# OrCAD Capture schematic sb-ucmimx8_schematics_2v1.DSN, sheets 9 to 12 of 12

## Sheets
9 08. PCIe: size A3; title: SB-UCM-iMX8M    08. PCIe; note: 8000103001
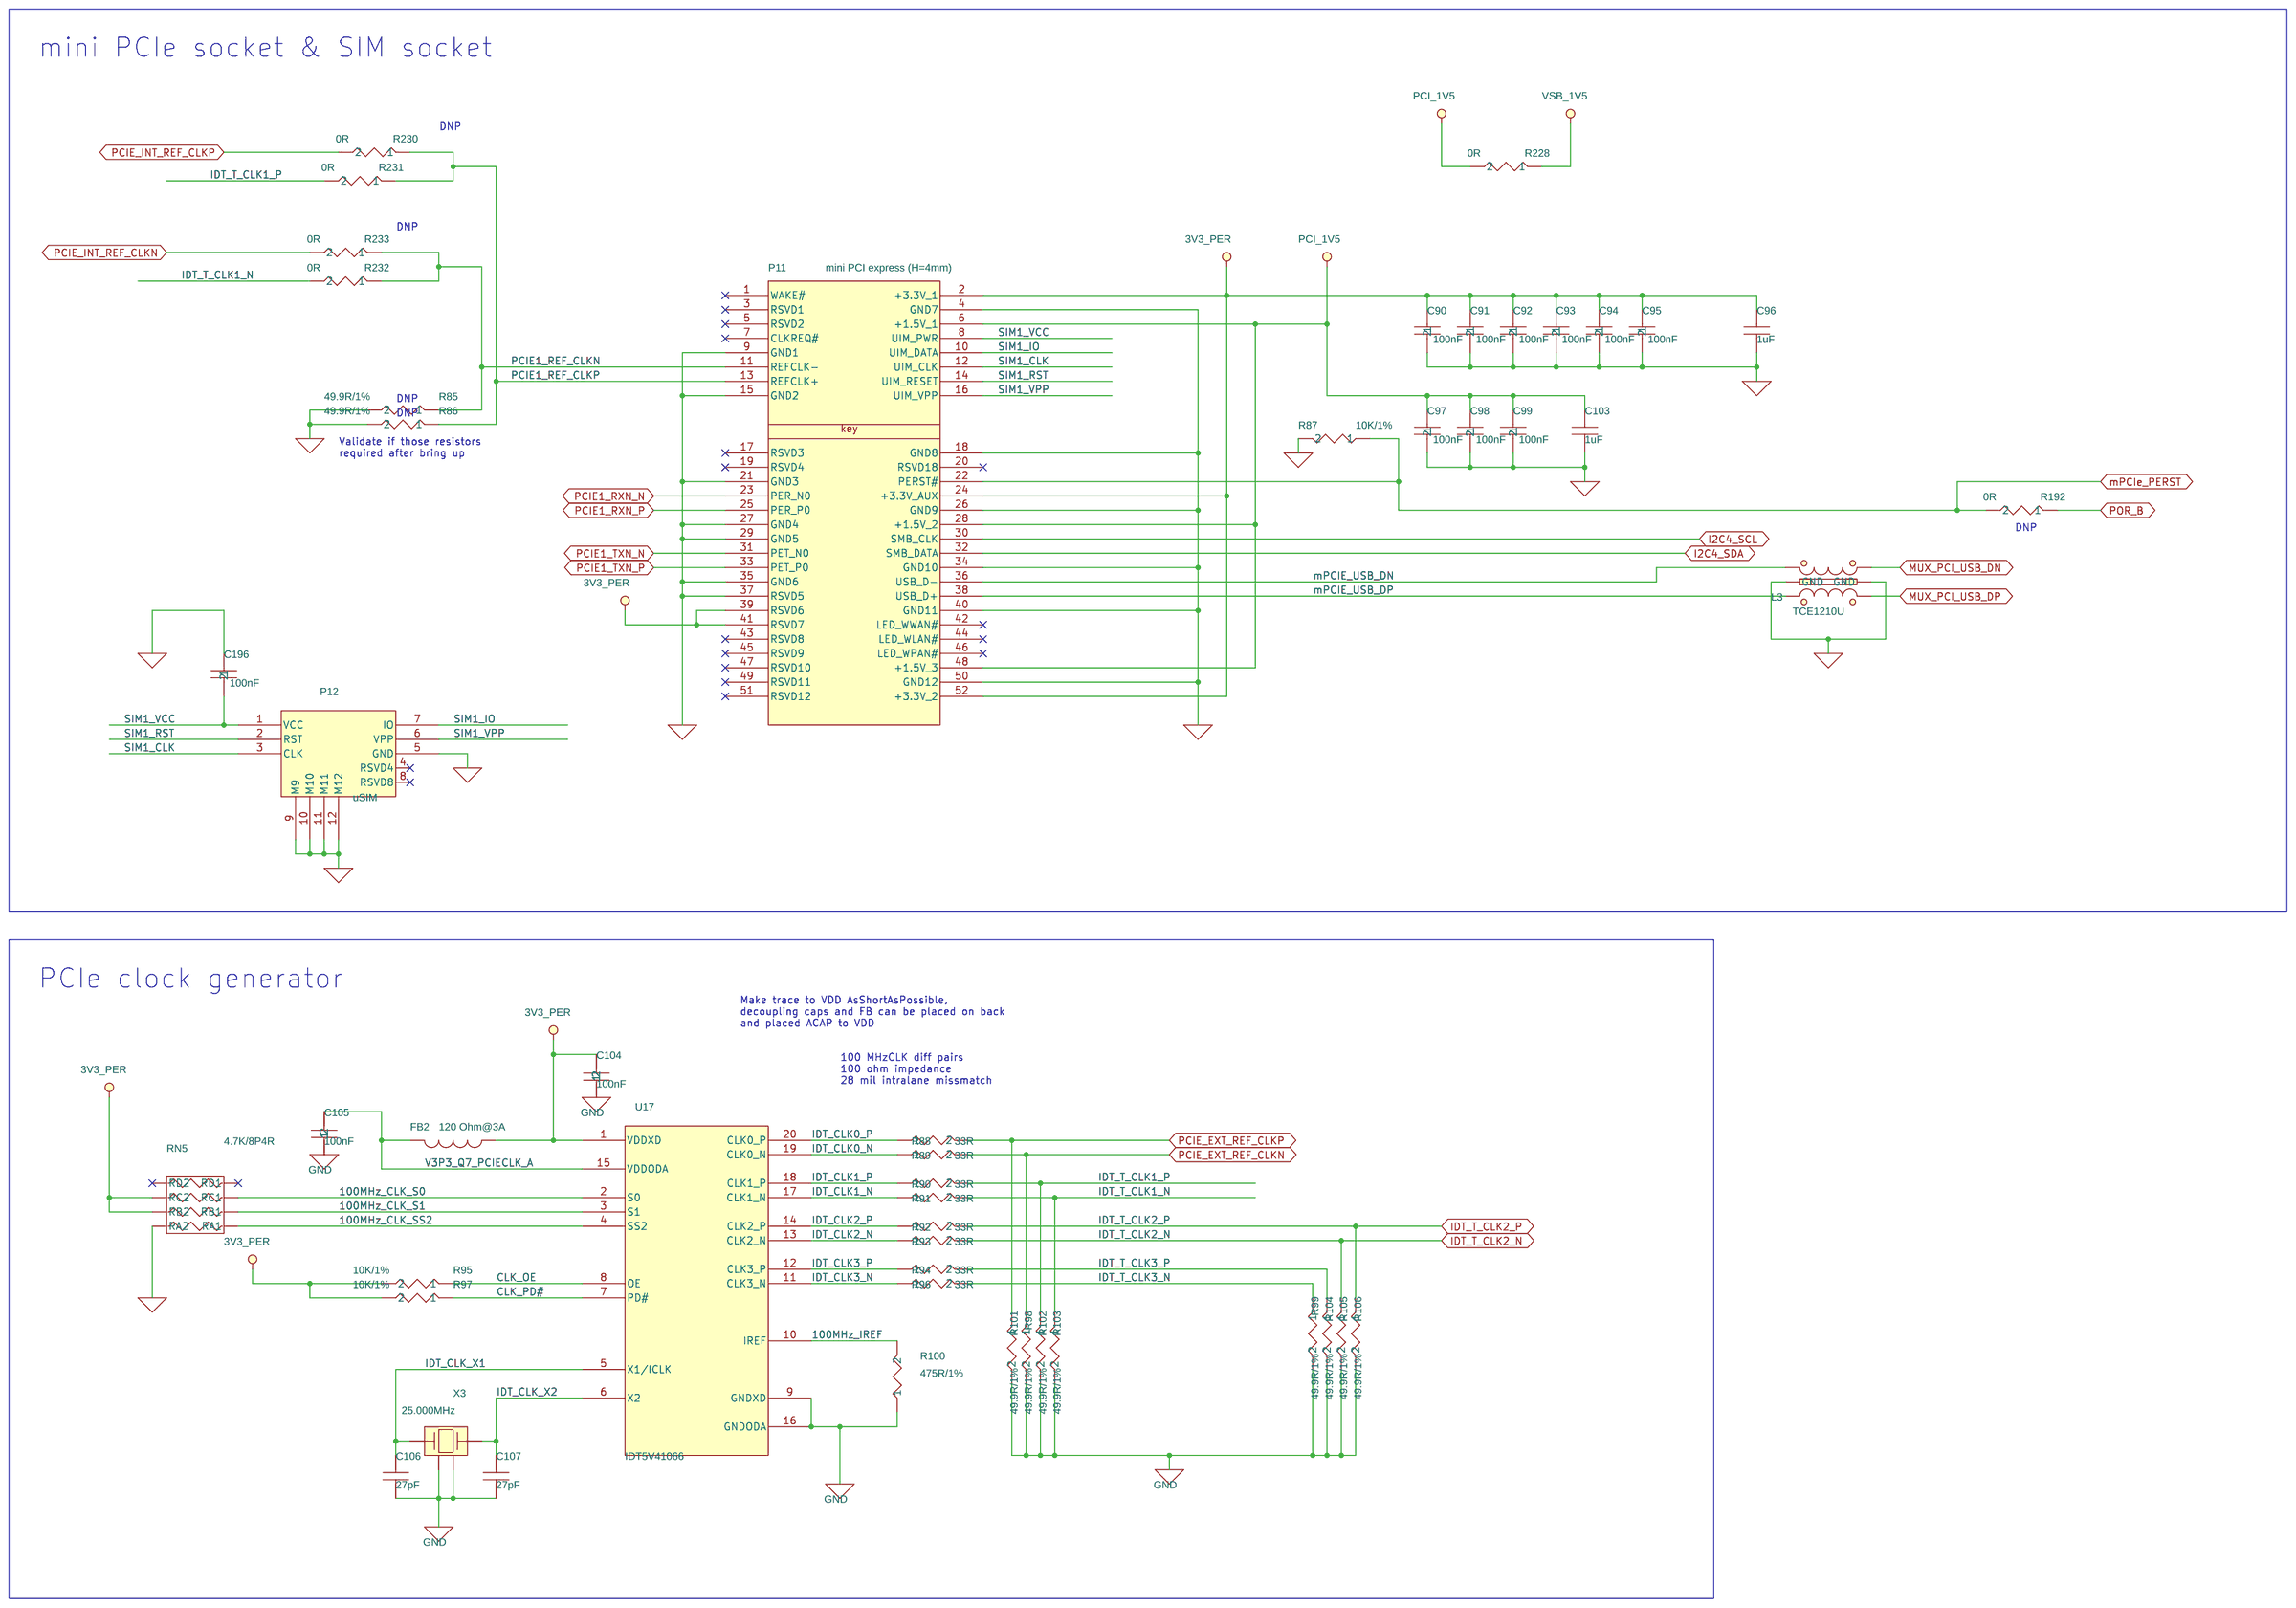
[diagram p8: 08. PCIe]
10 09. Power: size C; title: SB-UCM-iMX8M    09. POWER; note: 8000103001
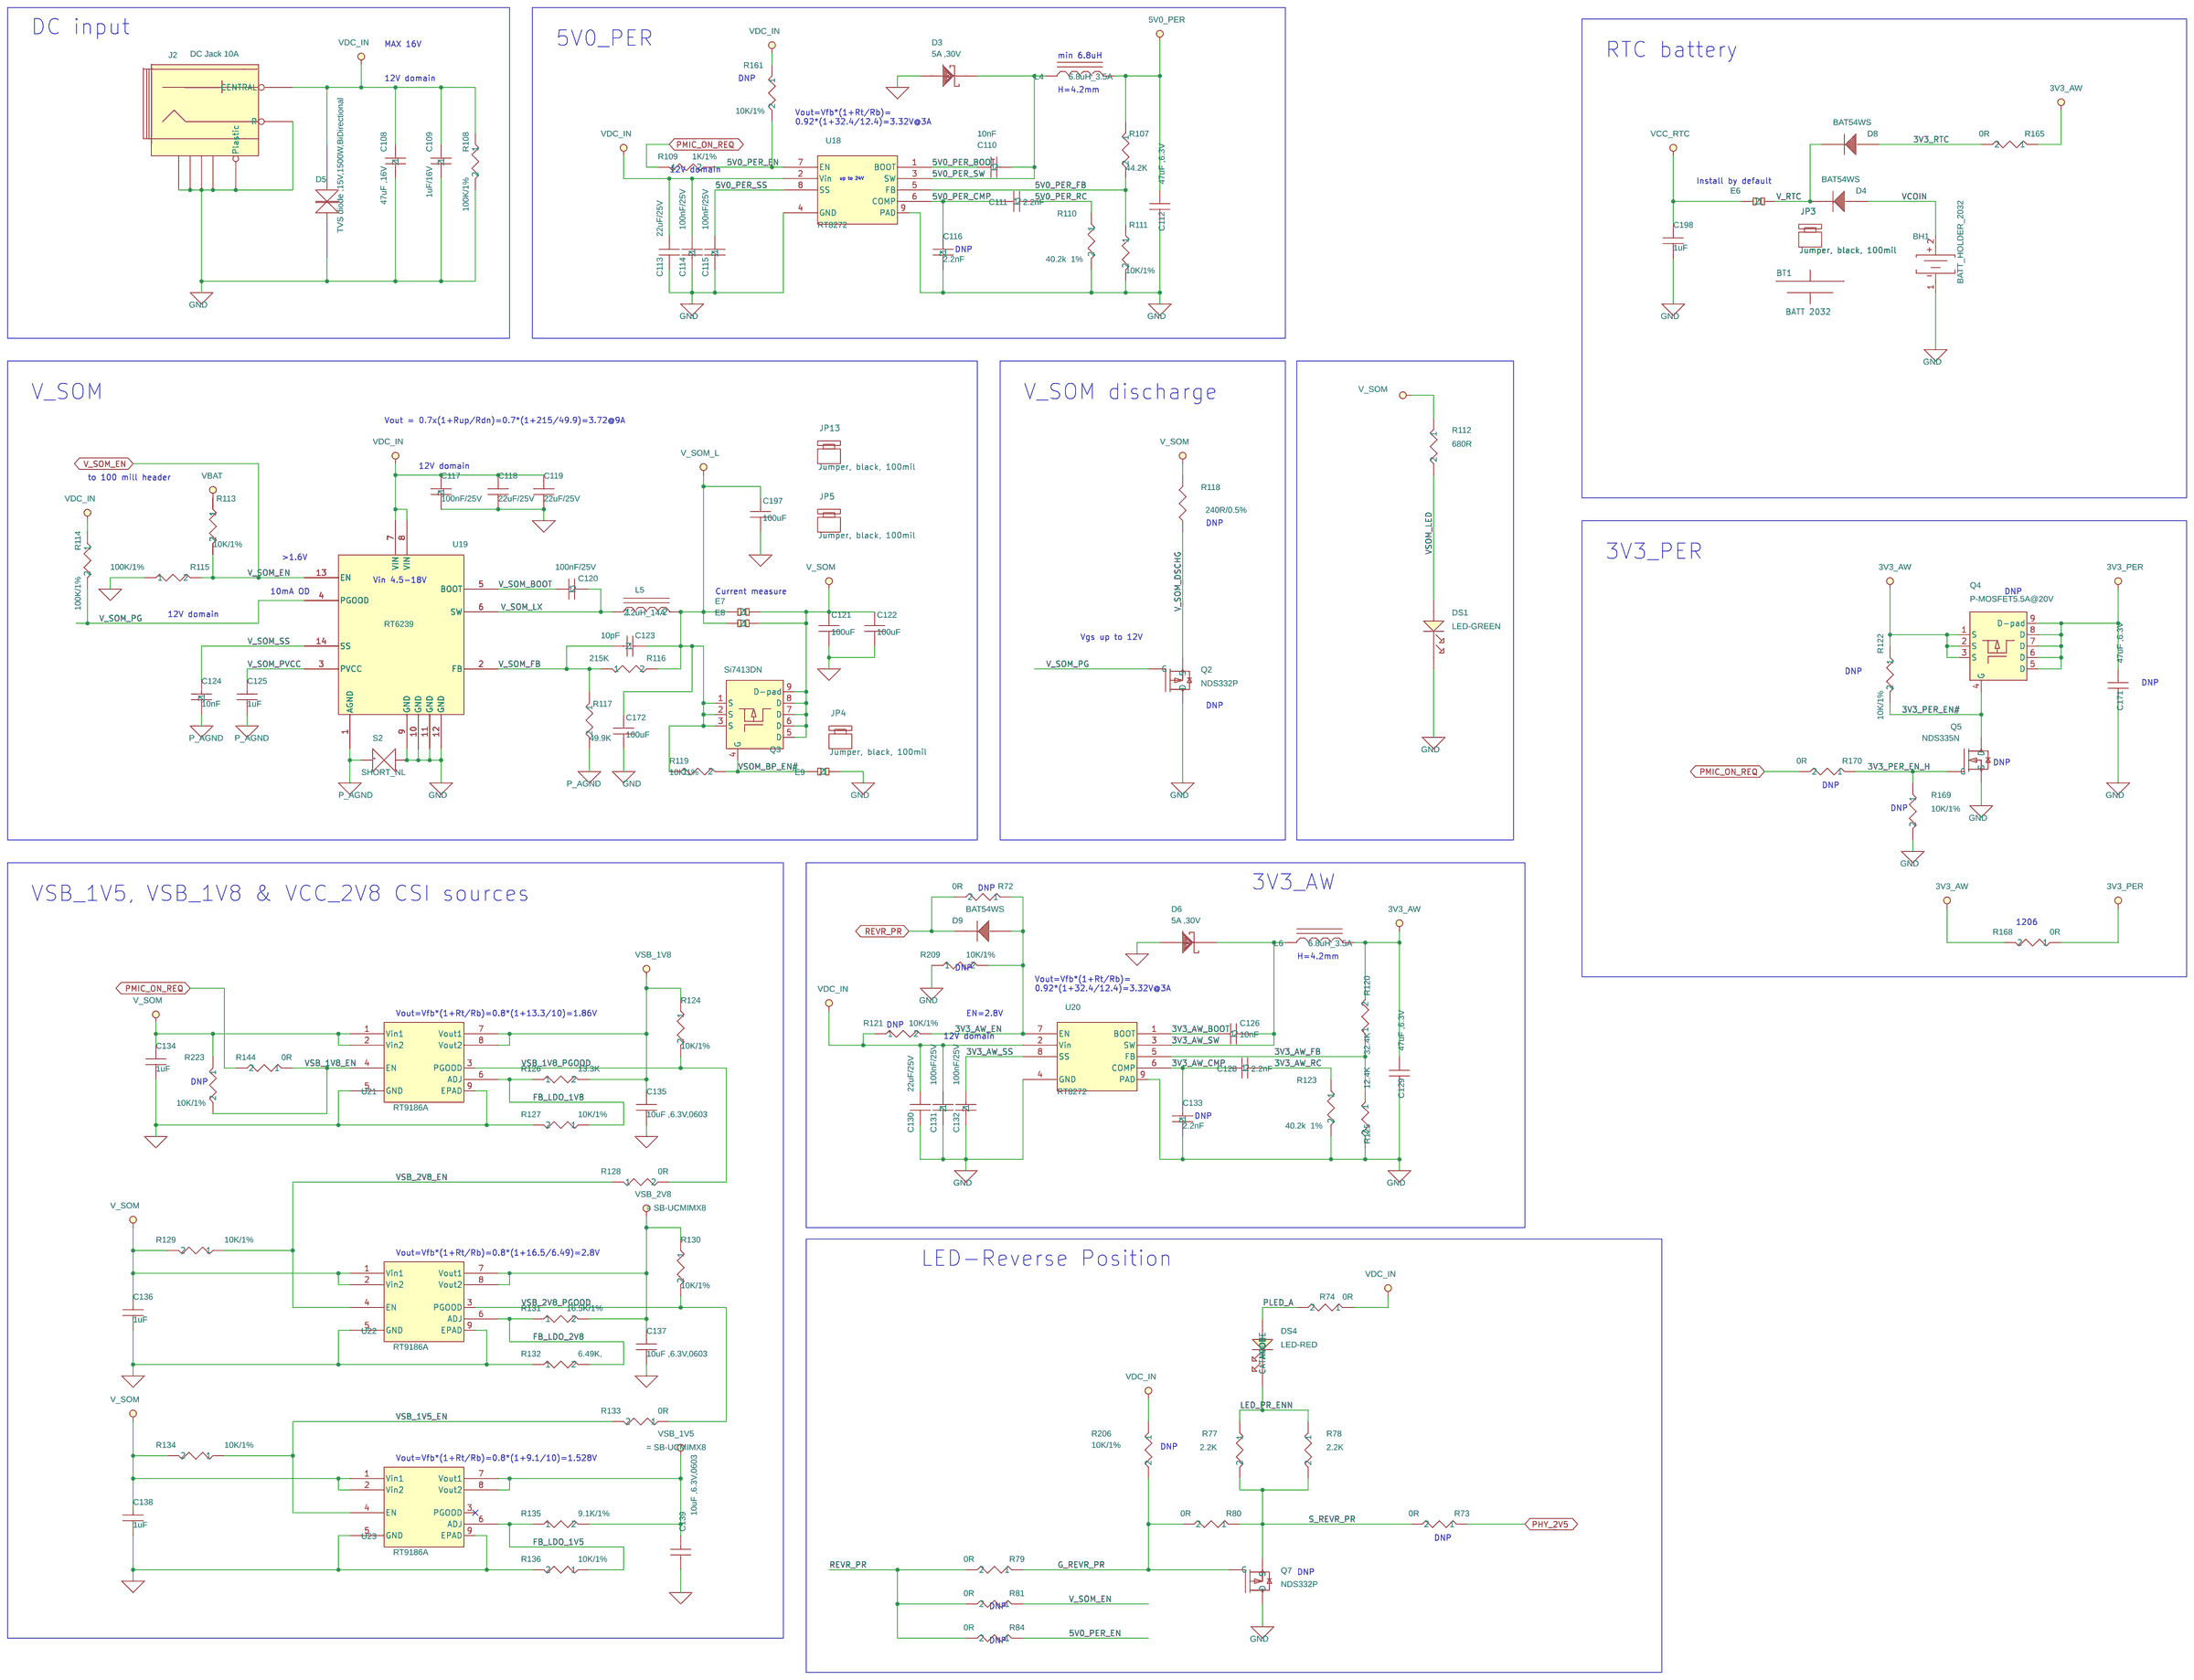
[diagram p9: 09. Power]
11 10. UART, RS232, SD, EEPROM: size C; title: SB-UCM-iMX8M      10. UART, RS232, SD Slot, EEPROM,GPIO; note: 8000103001
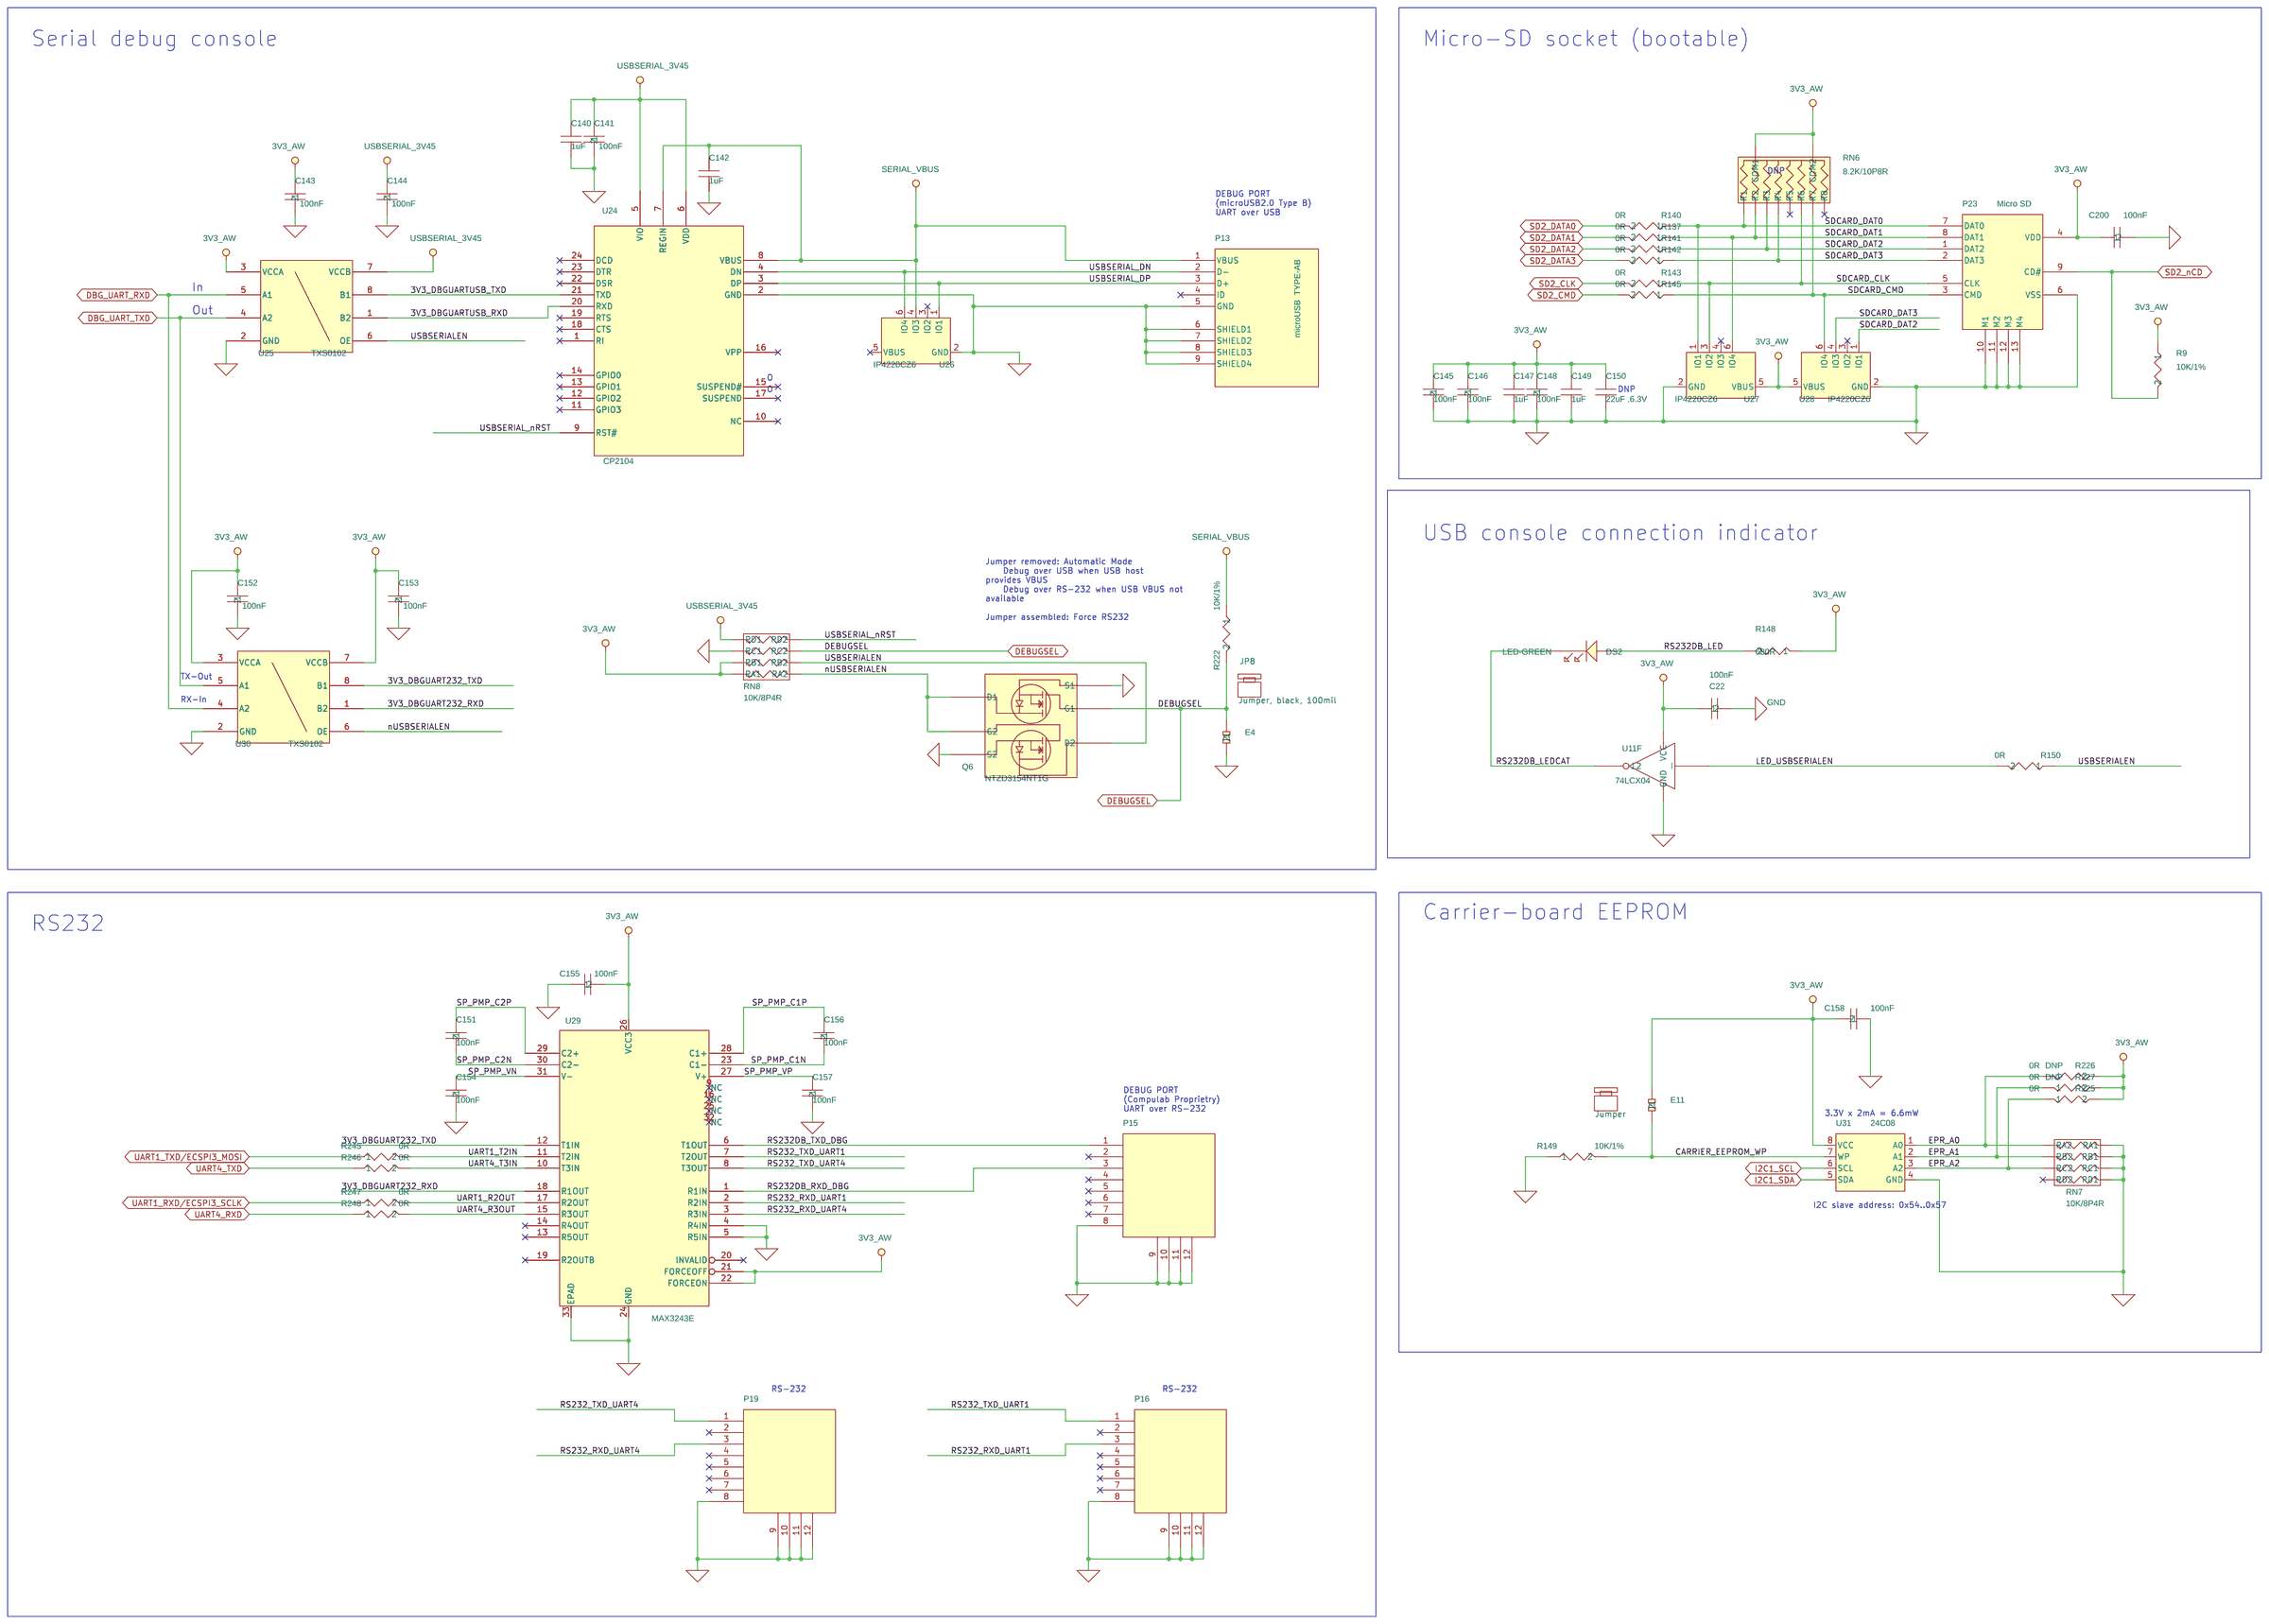
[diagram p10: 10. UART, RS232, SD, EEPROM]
12 11. Mechanical: size B; title: SB-UCM-iMX8M      11. Mechanical; note: 8000103001
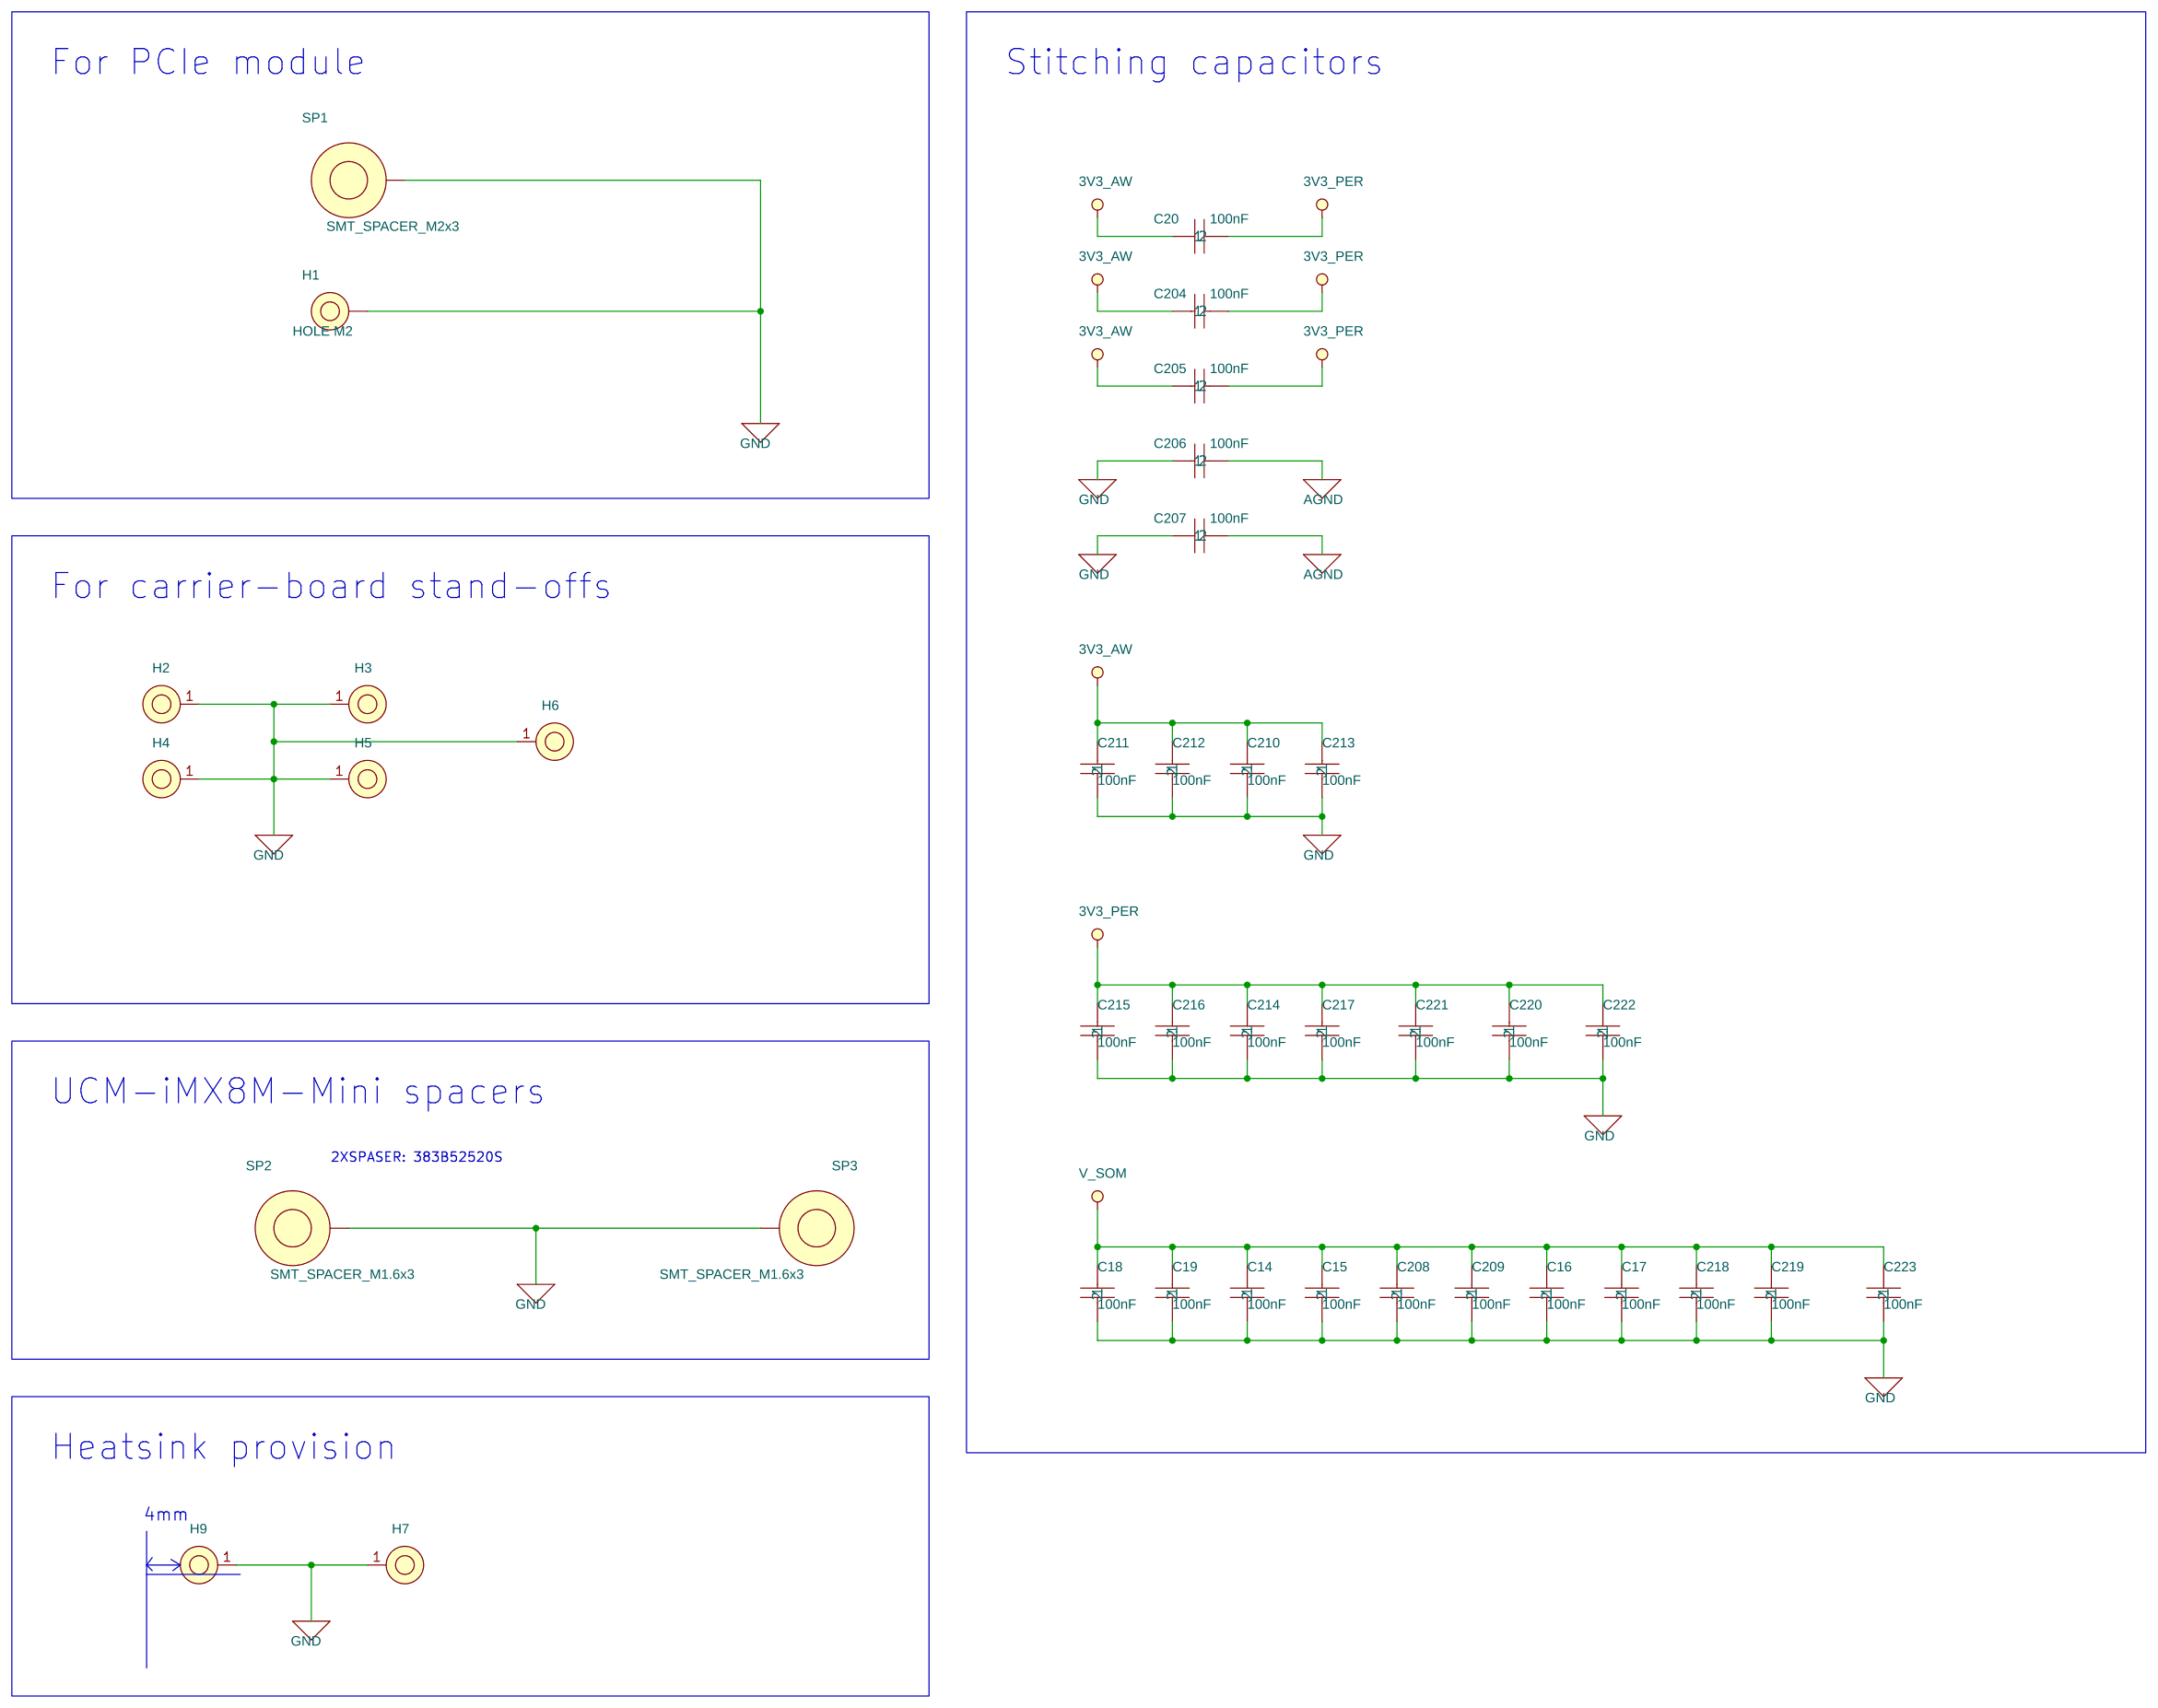
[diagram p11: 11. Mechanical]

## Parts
sheet 08. PCIe
C90  100nF  [RC0402]
C91  100nF  [RC0402]
C92  100nF  [RC0402]
C93  100nF  [RC0402]
C94  100nF  [RC0402]
C95  100nF  [RC0402]
C96  1uF  [RC0402]
C97  100nF  [RC0402]
C98  100nF  [RC0402]
C99  100nF  [RC0402]
C103  1uF  [RC0402]
C104  100nF  [RC0402]
C105  100nF  [RC0402]
C106  27pF  [RC0402]
C107  27pF  [RC0402]
C196  100nF  [RC0402]
FB2  120 Ohm@3A  [FB1206]
L3  TCE1210U  [EMI1012-ESD]
P11  mini PCI express (H=4mm)  [MINIPCIE-4]
P12  uSIM  [SKT-MicroSIM6-SM]
R85  49.9R/1%  [RC0402]
R86  49.9R/1%  [RC0402]
R87  10K/1%  [RC0402]
R88  33R  [RC0402]
R89  33R  [RC0402]
R90  33R  [RC0402]
R91  33R  [RC0402]
R92  33R  [RC0402]
R93  33R  [RC0402]
R94  33R  [RC0402]
R95  10K/1%  [RC0402]
R96  33R  [RC0402]
R97  10K/1%  [RC0402]
R98  49.9R/1%  [RC0402]
R99  49.9R/1%  [RC0402]
R100  475R/1%  [RC0402]
R101  49.9R/1%  [RC0402]
R102  49.9R/1%  [RC0402]
R103  49.9R/1%  [RC0402]
R104  49.9R/1%  [RC0402]
R105  49.9R/1%  [RC0402]
R106  49.9R/1%  [RC0402]
R192  0R  [RC0402]
R228  0R  [RC0402]
R230  0R  [RC0402]
R231  0R  [RC0402]
R232  0R  [RC0402]
R233  0R  [RC0402]
RN5  4.7K/8P4R  [RESNET8P0805]
U17  IDT5V41066  [TSSOP-20]
X3  25.000MHz  [OSC3225]
sheet 09. Power
BH1  BATT_HOLDER_2032  [BATTH20MM]
BT1  BATT 2032
C108  47uF ,16V  [C1210H2_5]
C109  1uF/16V  [RC0805]
C110  10nF  [RC0402]
C111  2.2nF  [RC0402]
C112  47uF ,6.3V  [C0805]
C113  22uF/25V  [C0805]
C114  100nF/25V  [RC0402]
C115  100nF/25V  [RC0402]
C116  2.2nF  [RC0402]
C117  100nF/25V  [RC0402]
C118  22uF/25V  [C0805]
C119  22uF/25V  [C0805]
C120  100nF/25V  [RC0402]
C121  100uF  [C1210H2_5]
C122  100uF  [C1210H2_5]
C123  10pF  [RC0402]
C124  10nF  [RC0402]
C125  1uF  [RC0402]
C126  10nF  [RC0402]
C128  2.2nF  [RC0402]
C129  47uF ,6.3V  [C0805]
C130  22uF/25V  [C0805]
C131  100nF/25V  [RC0402]
C132  100nF/25V  [RC0402]
C133  2.2nF  [RC0402]
C134  1uF  [RC0402]
C135  10uF ,6.3V,0603  [C0603-08]
C136  1uF  [RC0402]
C137  10uF ,6.3V,0603  [C0603-08]
C138  1uF  [RC0402]
C139  10uF ,6.3V,0603  [C0603-08]
C171  47uF ,6.3V  [C0805]
C172  100uF  [C1210H2_5]
C197  100uF  [C1210H2_5]
C198  1uF  [RC0402]
D3  5A ,30V  [SOD-128]
D4  BAT54WS  [SOD-323]
D5  TVS diode ,15V,1500W,BiDirectional  [DO-214AB]
D6  5A ,30V  [SOD-128]
D8  BAT54WS  [SOD-323]
D9  BAT54WS  [SOD-323]
DS1  LED-GREEN  [LED-1206]
DS4  LED-RED  [LED-1206]
E6  HDR1X2  [1X2THHDR]
E7  HDR1X2  [1X2THHDR]
E8  HDR1X2  [1X2THHDR]
E9  HDR1X2  [1X2THHDR]
J2  DC Jack 10A  [PJ-0810-TH]
JP3  Jumper, black, 100mil
JP4  Jumper, black, 100mil
JP5  Jumper, black, 100mil
JP13  Jumper, black, 100mil
L4  6.8uH_3.5A  [IND8_2x8_2]
L5  2.2uH_14A  [IND7x7_2SM]
L6  6.8uH_3.5A  [IND8_2x8_2]
Q2  NDS332P  [SOT23]
Q3  Si7413DN  [Powerpak1212-8]
Q4  P-MOSFET5.5A@20V  [Powerpak1212-8]
Q5  NDS335N  [SOT23]
Q7  NDS332P  [SOT23]
R72  0R  [RC0402]
R73  0R  [RC0402]
R74  0R  [RC0402]
R77  2.2K  [RC0402]
R78  2.2K  [RC0402]
R79  0R  [RC0402]
R80  0R  [RC0402]
R81  0R  [RC0402]
R84  0R  [RC0402]
R107  44.2K  [RC0402]
R108  100K/1%  [RC0402]
R109  1K/1%  [RC0402]
R110  40.2k  1%  [RC0402]
R111  10K/1%  [RC0402]
R112  680R  [RC0402]
R113  10K/1%  [RC0402]
R114  100K/1%  [RC0402]
R115  100K/1%  [RC0402]
R116  215K  [RC0402]
R117  49.9K  [RC0402]
R118  240R/0.5%  [RC0402]
R119  10K/1%  [RC0402]
R120  32.4K  [RC0402]
R121  10K/1%  [RC0402]
R122  10K/1%  [RC0402]
R123  40.2k  1%  [RC0402]
R124  10K/1%  [RC0402]
R125  12.4K  [RC0402]
R126  13.3K  [RC0402]
R127  10K/1%  [RC0402]
R128  0R  [RC0402]
R129  10K/1%  [RC0402]
R130  10K/1%  [RC0402]
R131  16.5K/1%  [RC0402]
R132  6.49K,  [RC0402]
R133  0R  [RC0402]
R134  10K/1%  [RC0402]
R135  9.1K/1%  [RC0402]
R136  10K/1%  [RC0402]
R144  0R  [RC0402]
R161  10K/1%  [RC0402]
R165  0R  [RC0402]
R168  0R  [RC1206]
R169  10K/1%  [RC0402]
R170  0R  [RC0402]
R206  10K/1%  [RC0402]
R209  10K/1%  [RC0402]
R223  10K/1%  [RC0402]
S2  SHORT_NL  [SHORT_NL]
U18  RT8272  [PSOP-8-2X2]
U19  RT6239  [uQFN2x3-14]
U20  RT8272  [PSOP-8-2X2]
U21  RT9186A  [DFN3x3-8]
U22  RT9186A  [DFN3x3-8]
U23  RT9186A  [DFN3x3-8]
sheet 10. UART, RS232, SD, EEPROM
C22  100nF  [RC0402]
C140  1uF  [RC0402]
C141  100nF  [RC0402]
C142  1uF  [RC0402]
C143  100nF  [RC0402]
C144  100nF  [RC0402]
C145  100nF  [RC0402]
C146  100nF  [RC0402]
C147  1uF  [RC0402]
C148  100nF  [RC0402]
C149  1uF  [RC0402]
C150  22uF ,6.3V  [RC0603]
C151  100nF  [RC0402]
C152  100nF  [RC0402]
C153  100nF  [RC0402]
C154  100nF  [RC0402]
C155  100nF  [RC0402]
C156  100nF  [RC0402]
C157  100nF  [RC0402]
C158  100nF  [RC0402]
C200  100nF  [RC0402]
DS2  LED-GREEN  [LED-1206]
E4  HDR1X2  [1X2THHDR]
E11  HDR1X2  [1X2THHDR]
JP6  Jumper
JP8  Jumper, black, 100mil
P13  microUSB  TYPE-AB  [MICRO-USB-AB-RA-SM]
P15  Ultra Mini Serial Connector  [UMS-8]
P16  Ultra Mini Serial Connector  [UMS-8]
P19  Ultra Mini Serial Connector  [UMS-8]
P23  Micro SD  [MicroSD-PP-RA-SM]
Q6  NTZD3154NT1G  [SOT-563]
R9  10K/1%  [RC0402]
R137  0R  [RC0402]
R140  0R  [RC0402]
R141  0R  [RC0402]
R142  0R  [RC0402]
R143  0R  [RC0402]
R145  0R  [RC0402]
R148  680R  [RC0402]
R149  10K/1%  [RC0402]
R150  0R  [RC0402]
R222  10K/1%  [RC0402]
R225  0R  [RC0402]
R226  0R  [RC0402]
R227  0R  [RC0402]
R245  0R  [RC0402]
R246  0R  [RC0402]
R247  0R  [RC0402]
R248  0R  [RC0402]
RN6  8.2K/10P8R  [RESNET10P1206]
RN7  10K/8P4R  [RESNET8P0805]
RN8  10K/8P4R  [RESNET8P0805]
U24  CP2104  [MO-220VGGD-8]
U25  TXS0102  [MO-187DA-8]
U26  IP4220CZ6  [SOT23-6L]
U27  IP4220CZ6  [SOT23-6L]
U28  IP4220CZ6  [SOT23-6L]
U29  MAX3243E  [QFN5x5-32]
U30  TXS0102  [MO-187DA-8]
U31  24C08  [MO-229VCED-2]
sheet 11. Mechanical
C14  100nF  [RC0402]
C15  100nF  [RC0402]
C16  100nF  [RC0402]
C17  100nF  [RC0402]
C18  100nF  [RC0402]
C19  100nF  [RC0402]
C20  100nF  [RC0402]
C204  100nF  [RC0402]
C205  100nF  [RC0402]
C206  100nF  [RC0402]
C207  100nF  [RC0402]
C208  100nF  [RC0402]
C209  100nF  [RC0402]
C210  100nF  [RC0402]
C211  100nF  [RC0402]
C212  100nF  [RC0402]
C213  100nF  [RC0402]
C214  100nF  [RC0402]
C215  100nF  [RC0402]
C216  100nF  [RC0402]
C217  100nF  [RC0402]
C218  100nF  [RC0402]
C219  100nF  [RC0402]
C220  100nF  [RC0402]
C221  100nF  [RC0402]
C222  100nF  [RC0402]
C223  100nF  [RC0402]
H1  HOLE M2  [M2PAD]
H2  MechHole  [M3PAD]
H3  MechHole  [M3PAD]
H4  MechHole  [M3PAD]
H5  MechHole  [M3PAD]
H6  MechHole  [M3PAD]
H7  MechHole  [OvalPad]
H9  MechHole  [OvalPad]
SP1  SMT_SPACER_M2x3  [MINIPCIE-4-Spacer]
SP2  SMT_SPACER_M1.6x3  [MINIPCIE-4-Spacer]
SP3  SMT_SPACER_M1.6x3  [MINIPCIE-4-Spacer]
sheet 12. ALT boot
U11  74LCX04  [TSSOP-14]  (sections A,B,C,D,E,F)

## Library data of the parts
C22 C90 = 100nF,_10V,_X7R,_10%,_0402_5: CLABCONF0: = SB-UCMIMX8
C91 C148 = 100nF,_10V,_X7R,_10%,_0402_8: CLABCONF0: = SB-UCMIMX8
C92 C151 = 100nF,_10V,_X7R,_10%,_0402: CLABCONF0: = SB-UCMIMX8
C93 C154 = 100nF,_10V,_X7R,_10%,_0402_7: CLABCONF0: = SB-UCMIMX8
C94 C146 = 100nF,_10V,_X7R,_10%,_0402_10: CLABCONF0: = SB-UCMIMX8
C95 C158 = 100nF,_10V,_X7R,_10%,_0402_2: CLABCONF0: = SB-UCMIMX8
C96 C103 C134 C136 C138 C140 C142 C147 C149 C198 = 1uF,X5R,6.3V,0402: CLABCONF0: = SB-UCMIMX8
C97 C143 = 100nF,_10V,_X7R,_10%,_0402_6: CLABCONF0: = SB-UCMIMX8
C98 C141 = 100nF,_10V,_X7R,_10%,_0402_9: CLABCONF0: = SB-UCMIMX8
C99 C200 = 100nF,_10V,_X7R,_10%,_0402_1: CLABCONF0: = SB-UCMIMX8
C104 C145 = 100nF,_10V,_X7R,_10%,_0402_3: CLABCONF0: = SB-UCMIMX8
C105 C157 = 100nF,_10V,_X7R,_10%,_0402_4: CLABCONF0: = SB-UCMIMX8
C106 C107 = 27pF,_50V,_X7R,_10%,_0402: CLABCONF0: = SB-UCMIMX8; P/N: 151D27000S
C153 C196 = 100nF,_10V,_X7R,_10%,_0402_11: CLABCONF0: = SB-UCMIMX8
FB2 = Ferrite_bead_,_120_Ohm@3A: CLABCONF0: = SB-UCMIMX8
L3 = ESD_CHOKE_DIFFx2_10: CLABCONF0: = SB-UCMIMX8; P/N: 142D11801S
P11 = mini_PCIe_0: CLABCONF0: = SB-UCMIMX8; P/N: 182K05201S
P12 = uSIM_SOCKET_0: CLABCONF0: = SB-UCMIMX8
R85 = 49.9R_1%,_0402_3: CLABCONF0: DNP
R86 = 49.9R_1%,_0402_4: CLABCONF0: DNP
R87 = 10K,1%,0402,1_16W_2: CLABCONF0: = SB-UCMIMX8
R88 = 33R,5%,0402,1_16W_1: CLABCONF0: = SB-UCMIMX8
R89 = 33R,5%,0402,1_16W_3: CLABCONF0: = SB-UCMIMX8
R90 = 33R,5%,0402,1_16W_6: CLABCONF0: = SB-UCMIMX8
R91 = 33R,5%,0402,1_16W_7: CLABCONF0: = SB-UCMIMX8
R92 = 33R,5%,0402,1_16W: CLABCONF0: = SB-UCMIMX8
R93 = 33R,5%,0402,1_16W_2: CLABCONF0: = SB-UCMIMX8
R94 = 33R,5%,0402,1_16W_5: CLABCONF0: = SB-UCMIMX8
R95 R149 = 10K,1%,0402,1_16W: CLABCONF0: = SB-UCMIMX8
R96 = 33R,5%,0402,1_16W_4: CLABCONF0: = SB-UCMIMX8
R97 R113 R222 = 10K,1%,0402,1_16W_1: CLABCONF0: = SB-UCMIMX8
R98 = 49.9R_1%,_0402_6: CLABCONF0: = SB-UCMIMX8
R99 = 49.9R_1%,_0402_9: CLABCONF0: = SB-UCMIMX8
R100 = 475R_1%,_0402: CLABCONF0: = SB-UCMIMX8
R101 = 49.9R_1%,_0402_5: CLABCONF0: = SB-UCMIMX8
R102 = 49.9R_1%,_0402_8: CLABCONF0: = SB-UCMIMX8
R103 = 49.9R_1%,_0402: CLABCONF0: = SB-UCMIMX8
R104 = 49.9R_1%,_0402_1: CLABCONF0: = SB-UCMIMX8
R105 = 49.9R_1%,_0402_2: CLABCONF0: = SB-UCMIMX8
R106 = 49.9R_1%,_0402_7: CLABCONF0: = SB-UCMIMX8
R192 = 0R,_0402_0_4: CLABCONF0: DNP; P/N: 161C00005S
R228 = 0R,_0402_0_5: CLABCONF0: = SB-UCMIMX8; P/N: 161C00005S
R81 R230 = 0R,_0402_0_2: CLABCONF0: DNP; P/N: 161C00005S
R165 R231 = 0R,_0402_0_3: CLABCONF0: = SB-UCMIMX8; P/N: 161C00005S
R232 = 0R,_0402_0: CLABCONF0: = SB-UCMIMX8; P/N: 161C00005S
R233 = 0R,_0402_0_1: CLABCONF0: DNP; P/N: 161C00005S
RN5 = RN,4.7K,8P4R@0805: CLABCONF0: = SB-UCMIMX8
U17 = IDT5V41066_0: CLABCONF0: = SB-UCMIMX8; P/N: 116A00120S
X3 = XTAL,_25.000Mhz,_3x5mm: CLABCONF0: = SB-UCMIMX8; P/N: 141B25603I
BH1 = BATT_HOLDER_0: CLABCONF0: = SB-UCMIMX8
BT1 = BATT_2032: CLABCONF0: = SB-UCMIMX8
C108 = Cap.,_47uF,_16V,_X5R: CLABCONF0: = SB-UCMIMX8
C109 = 1uF,_16V,_X7R,_20%,_0805: CLABCONF0: = SB-UCMIMX8
C110 = 10nF,_25V,_X7R,_10%,_0402_1: CLABCONF0: = SB-UCMIMX8
C111 = 2.2nF,_50V,_X7R,_10%,_0402: CLABCONF0: = SB-UCMIMX8
C112 = 47uF,6.3V,X5R: CLABCONF0: = SB-UCMIMX8
C113 = Cap.,22uF,25V,_0805: CLABCONF0: = SB-UCMIMX8
C114 = 100nF_0402_25V_5: CLABCONF0: = SB-UCMIMX8
C115 = 100nF_0402_25V_1: CLABCONF0: = SB-UCMIMX8
C116 = 2.2nF,_50V,_X7R,_10%,_0402_2: CLABCONF0: DNP
C117 = 100nF_0402_25V: CLABCONF0: = SB-UCMIMX8
C118 = 22uF,25V,_0805: CLABCONF0: = SB-UCMIMX8
C119 = 22uF,25V,_0805_1: CLABCONF0: = SB-UCMIMX8
C120 = 100nF_0402_25V_3: CLABCONF0: = SB-UCMIMX8
C121 C122 C172 C197 = 100uF,_6.3V,_X5R,_20%,_1206: CLABCONF0: = SB-UCMIMX8
C123 = 10pF,50V,NPO,_5%,_0402: CLABCONF0: = SB-UCMIMX8
C124 = 10nF,_25V,_X7R,_10%,_0402: CLABCONF0: = SB-UCMIMX8
C125 = 1uF,16V,0402: CLABCONF0: = SB-UCMIMX8
C126 = 10nF,_25V,_X7R,_10%,_0402_2: CLABCONF0: = SB-UCMIMX8
C128 = 2.2nF,_50V,_X7R,_10%,_0402_1: CLABCONF0: = SB-UCMIMX8
C129 = 47uF,6.3V,X5R_2: CLABCONF0: = SB-UCMIMX8
C130 = Cap.,22uF,25V,_0805_1: CLABCONF0: = SB-UCMIMX8
C131 = 100nF_0402_25V_4: CLABCONF0: = SB-UCMIMX8
C132 = 100nF_0402_25V_2: CLABCONF0: = SB-UCMIMX8
C133 = 2.2nF,_50V,_X7R,_10%,_0402_3: CLABCONF0: = SB-UCMIMX8
C135 C137 C139 = 10uF,6_0.3V,0603,20%X5R: CLABCONF0: = SB-UCMIMX8
C171 = 47uF,6.3V,X5R_1: CLABCONF0: DNP
D3 D6 = Diode_Shotky,5A,30V: CLABCONF0: = SB-UCMIMX8
D4 D8 D9 = BAT54WS_0: CLABCONF0: = SB-UCMIMX8
D5 = Diode_,TVS_,15V,1500W_0: CLABCONF0: = SB-UCMIMX8; P/N: 132D00150S
DS1 DS2 = LED-GREEN_1206_3: CLABCONF0: = SB-UCMIMX8
DS4 = LED-RED_1206: CLABCONF0: = SB-UCMIMX8
E6 = HDR_1x2_100MIL_TH_JUMPER_3: CLABCONF0: = SB-UCMIMX8
E7 = HDR_1x2_100MIL_TH_JUMPER_2: CLABCONF0: = SB-UCMIMX8
E8 E11 = HDR_1x2_100MIL_TH_JUMPER_1: CLABCONF0: = SB-UCMIMX8
E4 E9 = HDR_1x2_100MIL_TH_JUMPER: CLABCONF0: = SB-UCMIMX8
J2 = DC_Jack_,5.5_2_0.5,10A,20V: CLABCONF0: = SB-UCMIMX8
JP3-JP5 JP13 = Jumper,_black,_100mil: CLABCONF0: = SB-UCMIMX8
L4 L6 = IND_6.8uH_3.5A: CLABCONF0: = SB-UCMIMX8; P/N: 147A6R801S
L5 = IND_DELTA_MPL73-2R2_2.2uH_14A: CLABCONF0: = SB-UCMIMX8
Q2 Q7 = P-MOSFET,3A,20V,110mOhm@-1.8V: CLABCONF0: DNP
Q3 = Si7413DN: CLABCONF0: = SB-UCMIMX8
Q4 = MOSFET_P,_5.5A_20V: CLABCONF0: DNP
Q5 = N-MOSFET,NDS335N,100mOhm@2.5V: CLABCONF0: DNP
R72 = 0R,_0402_0_7: CLABCONF0: DNP; P/N: 161C00005S
R73 = 0R,_0402_0: CLABCONF0: DNP; P/N: 161C00005S
R74 = 0R,_0402_0_8: CLABCONF0: = SB-UCMIMX8; P/N: 161C00005S
R77 = 2.2K,5%,0402.1_16W: CLABCONF0: = SB-UCMIMX8
R78 = 2.2K,5%,0402.1_16W_1: CLABCONF0: = SB-UCMIMX8
R79 = 0R,_0402_0_4: CLABCONF0: = SB-UCMIMX8; P/N: 161C00005S
R80 = 0R,_0402_0_1: CLABCONF0: = SB-UCMIMX8; P/N: 161C00005S
R84 = 0R,_0402_0_5: CLABCONF0: DNP; P/N: 161C00005S
R107 = 100K,_0402_1: CLABCONF0: = SB-UCMIMX8; P/N: 161C44221S
R108 = 100K,_1%,_0402,_1_16W_1: CLABCONF0: = SB-UCMIMX8
R109 = 1K,1%,0402,1_16W: CLABCONF0: = SB-UCMIMX8; Group: CAN
R110 = 40.2k_,1%: CLABCONF0: = SB-UCMIMX8
R111 = 10K,1%,0402,1_16W_12: CLABCONF0: = SB-UCMIMX8
R112 R148 = 47K,_0402: CLABCONF0: = SB-UCMIMX8; P/N: 161C68001S
R114 = 100K,_1%,_0402,_1_16W_2: CLABCONF0: = SB-UCMIMX8
R115 = 100K,_1%,_0402,_1_16W: CLABCONF0: = SB-UCMIMX8
R116 = 100K,_0402: CLABCONF0: = SB-UCMIMX8; P/N: 161C21531S
R117 = 100K,_0402_2: CLABCONF0: = SB-UCMIMX8; P/N: 161C49921S
R118 = 240R_resistor,_%0.5: CLABCONF0: DNP; P/N: 161C24003S
R119 = 10K,1%,0402,1_16W_10: CLABCONF0: = SB-UCMIMX8
R120 = 32.4K,_0402: CLABCONF0: = SB-UCMIMX8; P/N: 161C32421S
R121 = 10K,1%,0402,1_16W: CLABCONF0: DNP
R122 = 10K,1%,0402,1_16W_9: CLABCONF0: DNP
R123 = 40.2k_,1%_1: CLABCONF0: = SB-UCMIMX8
R124 = 10K,1%,0402,1_16W_4: CLABCONF0: = SB-UCMIMX8
R125 = 4.99K,1%,0402,1_16W: CLABCONF0: = SB-UCMIMX8; P/N: 161C12421S
R126 = 13.3K,_0402_tmp: CLABCONF0: = SB-UCMIMX8; P/N: 161C13321S
R127 = 10K,1%,0402,1_16W_14: CLABCONF0: = SB-UCMIMX8
R128 R225 R246 = 0R,_0402_1: CLABCONF0: = SB-UCMIMX8
R129 = 10K,1%,0402,1_16W_6: CLABCONF0: = SB-UCMIMX8
R130 = 10K,1%,0402,1_16W_15: CLABCONF0: = SB-UCMIMX8
R131 = 10K,1%,0402,1_16W_7: CLABCONF0: = SB-UCMIMX8; P/N: 161C16521S
R132 = 33R,5%,0402,1_16W: CLABCONF0: = SB-UCMIMX8; P/N: 161C64911S
R133 = 0R,_0402_1_2: CLABCONF0: = SB-UCMIMX8
R134 = 10K,1%,0402,1_16W_13: CLABCONF0: = SB-UCMIMX8
R135 = 953R,1%,0402,1_16W_0: CLABCONF0: = SB-UCMIMX8; P/N: 161C91011S
R136 = 10K,1%,0402,1_16W_5: CLABCONF0: = SB-UCMIMX8
R144 R150 = 0R,_0402_1_1: CLABCONF0: = SB-UCMIMX8
R161 = 10K,1%,0402,1_16W_3: CLABCONF0: DNP
R168 = 0R,_1206: CLABCONF0: = SB-UCMIMX8
R169 = 10K,1%,0402,1_16W_0: CLABCONF0: DNP
R170 = 0R,_0402_0_6: CLABCONF0: DNP; P/N: 161C00005S
R206 = 10K,1%,0402,1_16W_8: CLABCONF0: DNP
R209 = 10K,1%,0402,1_16W_2: CLABCONF0: DNP
R223 = 10K,1%,0402,1_16W_11: CLABCONF0: DNP
S2 = MISC_SHORT_NL: CLABCONF0: DNP
U18 U20 = RT8272,Converter,3A,24V: CLABCONF0: = SB-UCMIMX8
U19 = RT6239A_B: CLABCONF0: = SB-UCMIMX8; P/N: 123V08000S
U21-U23 = RT9186A,LDO_,2.5-5_0.5V,500mA: CLABCONF0: = SB-UCMIMX8
C144 = 100nF,_10V,_X7R,_10%,_0402_13: CLABCONF0: = SB-UCMIMX8
C150 = 22uF,6.3V,X5R: CLABCONF0: = SB-UCMIMX8; P/N: 151B22610S
C152 = 100nF,_10V,_X7R,_10%,_0402_12: CLABCONF0: = SB-UCMIMX8
C155 = 100nF,_10V,_X7R,_10%,_0402_14: CLABCONF0: = SB-UCMIMX8
C156 = 100nF,_10V,_X7R,_10%,_0402_15: CLABCONF0: = SB-UCMIMX8
JP6 JP8 = Jumper,_black,_100mil_0: CLABCONF0: = SB-UCMIMX8
P13 = Conn.,_Micro-USB,_B-Type: CLABCONF0: = SB-UCMIMX8; P/N: 180K00501S
P15 P16 P19 = Ultra_Mini_Serial_Connector: CLABCONF0: = SB-UCMIMX8
P23 = microSD_push-pull_1: CLABCONF0: = SB-UCMIMX8; P/N: 182K00803S
Q6 = MOSFET_N_DUAL_0_0.4A_20V: CLABCONF0: = SB-UCMIMX8
R9 = 10K,1%,0402,1_16W_0: CLABCONF0: = SB-UCMIMX8
R137 = 0R,_0402_1_9: CLABCONF0: = SB-UCMIMX8
R140 = 0R,_0402_1_8: CLABCONF0: = SB-UCMIMX8
R141 = 0R,_0402_1_3: CLABCONF0: = SB-UCMIMX8
R142 = 0R,_0402_1_6: CLABCONF0: = SB-UCMIMX8
R143 = 0R,_0402_1_5: CLABCONF0: = SB-UCMIMX8
R145 = 0R,_0402_1_7: CLABCONF0: = SB-UCMIMX8
R226 = 0R,_0402_1_2: CLABCONF0: DNP
R227 = 0R,_0402_1_4: CLABCONF0: DNP
R245 = 0R,_0402: CLABCONF0: = SB-UCMIMX8
R247 = 0R,_0402_2: CLABCONF0: = SB-UCMIMX8
R248 = 0R,_0402_3: CLABCONF0: = SB-UCMIMX8
RN6 = RN,8.2K,10P8R@1206: CLABCONF0: DNP
RN7 RN8 = RN,10K,8P4R@0805: CLABCONF0: = SB-UCMIMX8
U24 = CP2104_0: CLABCONF0: = SB-UCMIMX8; P/N: 116A00140S
U25 U30 = TXS0102_0: CLABCONF0: = SB-UCMIMX8; P/N: 116A01020S
U26-U28 = IP4220CZ6_0: CLABCONF0: = SB-UCMIMX8
U29 = MAX3243E_RS-232_3T5R_BGA: CLABCONF0: = SB-UCMIMX8
U31 = 24C02,_serial_EE,_2KB,_I2C: CLABCONF0: = SB-UCMIMX8; P/N: 111S31000S
C14 = 100nF,_10V,_X7R,_10%,_0402_16: CLABCONF0: = SB-UCMIMX8; P/N: 151B10400S
C15 = 100nF,_10V,_X7R,_10%,_0402_23: CLABCONF0: = SB-UCMIMX8; P/N: 151B10400S
C16 = 100nF,_10V,_X7R,_10%,_0402_9: CLABCONF0: = SB-UCMIMX8; P/N: 151B10400S
C17 = 100nF,_10V,_X7R,_10%,_0402_18: CLABCONF0: = SB-UCMIMX8; P/N: 151B10400S
C18 = 100nF,_10V,_X7R,_10%,_0402_21: CLABCONF0: = SB-UCMIMX8; P/N: 151B10400S
C19 = 100nF,_10V,_X7R,_10%,_0402_24: CLABCONF0: = SB-UCMIMX8; P/N: 151B10400S
C20 = 100nF,_10V,_X7R,_10%,_0402_15: CLABCONF0: = SB-UCMIMX8; P/N: 151B10400S
C204 = 100nF,_10V,_X7R,_10%,_0402_1: CLABCONF0: = SB-UCMIMX8; P/N: 151B10400S
C205 = 100nF,_10V,_X7R,_10%,_0402_20: CLABCONF0: = SB-UCMIMX8; P/N: 151B10400S
C206 = 100nF,_10V,_X7R,_10%,_0402_22: CLABCONF0: = SB-UCMIMX8; P/N: 151B10400S
C207 = 100nF,_10V,_X7R,_10%,_0402_8: CLABCONF0: = SB-UCMIMX8; P/N: 151B10400S
C208 = 100nF,_10V,_X7R,_10%,_0402_11: CLABCONF0: = SB-UCMIMX8; P/N: 151B10400S
C209 = 100nF,_10V,_X7R,_10%,_0402_13: CLABCONF0: = SB-UCMIMX8; P/N: 151B10400S
C210 = 100nF,_10V,_X7R,_10%,_0402: CLABCONF0: = SB-UCMIMX8; P/N: 151B10400S
C211 = 100nF,_10V,_X7R,_10%,_0402_2: CLABCONF0: = SB-UCMIMX8; P/N: 151B10400S
C212 = 100nF,_10V,_X7R,_10%,_0402_5: CLABCONF0: = SB-UCMIMX8; P/N: 151B10400S
C213 = 100nF,_10V,_X7R,_10%,_0402_7: CLABCONF0: = SB-UCMIMX8; P/N: 151B10400S
C214 = 100nF,_10V,_X7R,_10%,_0402_10: CLABCONF0: = SB-UCMIMX8; P/N: 151B10400S
C215 = 100nF,_10V,_X7R,_10%,_0402_12: CLABCONF0: = SB-UCMIMX8; P/N: 151B10400S
C216 = 100nF,_10V,_X7R,_10%,_0402_17: CLABCONF0: = SB-UCMIMX8; P/N: 151B10400S
C217 = 100nF,_10V,_X7R,_10%,_0402_19: CLABCONF0: = SB-UCMIMX8; P/N: 151B10400S
C218 = 100nF,_10V,_X7R,_10%,_0402_26: CLABCONF0: = SB-UCMIMX8; P/N: 151B10400S
C219 = 100nF,_10V,_X7R,_10%,_0402_4: CLABCONF0: = SB-UCMIMX8; P/N: 151B10400S
C220 = 100nF,_10V,_X7R,_10%,_0402_3: CLABCONF0: = SB-UCMIMX8; P/N: 151B10400S
C221 = 100nF,_10V,_X7R,_10%,_0402_6: CLABCONF0: = SB-UCMIMX8; P/N: 151B10400S
C222 = 100nF,_10V,_X7R,_10%,_0402_25: CLABCONF0: = SB-UCMIMX8; P/N: 151B10400S
C223 = 100nF,_10V,_X7R,_10%,_0402_14: CLABCONF0: = SB-UCMIMX8; P/N: 151B10400S
H1 = Hole,_Plated,_M2,_5mm._ext.: CLABCONF0: DNP
H2-H7 H9 = Mechanical_Hole: CLABCONF0: DNP
SP1 = SMT_SPACER_M2x3: CLABCONF0: DNP
SP2 SP3 = SMT_SPACER_M2x3: CLABCONF0: = SB-UCMIMX8; P/N: 383B70030S
U11 = 74LCX04_sgl_gate_TSSOP-14: CLABCONF0: = SB-UCMIMX8

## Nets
3V3_AW: C20.1 C22.1 C129.1 C143.1 C145.1 C146.1 C147.1 C148.1 C149.1 C150.1 C152.1 C153.1 C155.2 C158.2 C200.1 C204.1 C205.1 C210.1 C211.1 C212.1 C213.1 E11.1 L6.2 P23.4(VDD) Q4.1(S) Q4.2(S) Q4.3(S) R9.1 R113.1 R120.2 R122.1 R148.1 R165.1 R168.2 R225.2 R226.2 R227.2 RN6.5(COM1) RN6.10(COM2) RN8.1(RA1) RN8.2(RB1) U25.3(VCCA) U27.5(VBUS) U28.5(VBUS) U29.21(FORCEOFF) U29.22(FORCEON) U29.26(VCC3) U30.3(VCCA) U30.7(VCCB) U31.8(VCC) ; also on sheet 2 4 5 7
3V3_AW_BOOT: C126.1 U20.1(BOOT)
3V3_AW_CMP: C128.1 C133.1 U20.6(COMP)
3V3_AW_EN: D9.ANODE R72.1 R121.2 R209.2 U20.7(EN)
3V3_AW_FB: R120.1 R125.1 U20.5(FB)
3V3_AW_RC: C128.2 R123.1
3V3_AW_SS: C132.1 U20.8(SS)
3V3_AW_SW: C126.2 D6.CATHODE L6.1 U20.3(SW)
3V3_DBGUART232_RXD: U29.18(R1OUT) U30.1(B2)
3V3_DBGUART232_TXD: U29.12(T1IN) U30.8(B1)
3V3_DBGUARTUSB_RXD: U24.20(RXD) U25.1(B2)
3V3_DBGUARTUSB_TXD: U24.21(TXD) U25.8(B1)
3V3_PER: C20.2 C90.1 C91.1 C92.1 C93.1 C94.1 C95.1 C96.1 C104.2 C171.1 C204.2 C205.2 C214.1 C215.1 C216.1 C217.1 C220.1 C221.1 C222.1 FB2.1 P11.2(+3.3V_1) P11.24(+3.3V_AUX) P11.39(RSVD6) P11.41(RSVD7) P11.52(+3.3V_2) Q4.5(D) Q4.6(D) Q4.7(D) Q4.8(D) Q4.9(D-pad) R95.2 R97.2 R168.1 RN5.6(RC2) RN5.7(RB2) U17.1(VDDXD) ; also on sheet 4 6 7 8
3V3_PER_EN#: Q4.4(G) Q5.3(D) R122.2
3V3_PER_EN_H: Q5.1(G) R169.1 R170.1
3V3_RTC: D8.ANODE R165.2
5V0_PER: C112.1 L4.2 R107.1 ; also on sheet 4 7
5V0_PER_BOOT: C110.1 U18.1(BOOT)
5V0_PER_CMP: C111.1 C116.1 U18.6(COMP)
5V0_PER_EN: R84.1 R109.2 R161.2 U18.7(EN)
5V0_PER_FB: R107.2 R111.1 U18.5(FB)
5V0_PER_RC: C111.2 R110.1
5V0_PER_SS: C115.1 U18.8(SS)
5V0_PER_SW: C110.2 D3.CATHODE L4.1 U18.3(SW)
AGND: C206.2 C207.2 ; also on sheet 6
GND: BH1.1(MINUS) C14.2 C15.2 C16.2 C17.2 C18.2 C19.2 C22.2 C90.2 C91.2 C92.2 C93.2 C94.2 C95.2 C96.2 C97.2 C98.2 C99.2 C103.2 C104.1 C105.1 C106.2 C107.2 C108.2 C109.2 C112.2 C113.2 C114.2 C115.2 C116.2 C117.2 C118.2 C119.2 C121.1 C122.1 C129.2 C130.2 C131.2 C132.2 C133.2 C134.2 C135.2 C136.2 C137.2 C138.2 C139.2 C140.2 C141.2 C142.2 C143.2 C144.2 C145.2 C146.2 C147.2 C148.2 C149.2 C150.2 C152.2 C153.2 C154.2 C155.1 C157.2 C158.1 C171.2 C172.1 C196.1 C197.1 C198.2 C200.2 C206.1 C207.1 C208.2 C209.2 C210.2 C211.2 C212.2 C213.2 C214.2 C215.2 C216.2 C217.2 C218.2 C219.2 C220.2 C221.2 C222.2 C223.2 D3.ANODE D5.ANODE D6.ANODE DS1.CATHODE E4.2 E9.1 H1.1 H2.1 H3.1 H4.1 H5.1 H6.1 H7.1 H9.1 J2.2(R) J2.3(Plastic) J2.SH1 J2.SH2 J2.SH3 J2.SH4 L3.5(GND) L3.6(GND) P11.4(GND7) P11.9(GND1) P11.15(GND2) P11.18(GND8) P11.21(GND3) P11.26(GND9) P11.27(GND4) P11.29(GND5) P11.34(GND10) P11.35(GND6) P11.37(RSVD5) P11.40(GND11) P11.50(GND12) P12.5(GND) P12.9(M9) P12.10(M10) P12.11(M11) P12.12(M12) P13.5(GND) P13.6(SHIELD1) P13.7(SHIELD2) P13.8(SHIELD3) P13.9(SHIELD4) P15.8 P15.9(CHASSIS) P15.10(CHASSIS) P15.11(CHASSIS) P15.12(CHASSIS) P16.8 P16.9(CHASSIS) P16.10(CHASSIS) P16.11(CHASSIS) P16.12(CHASSIS) P19.8 P19.9(CHASSIS) P19.10(CHASSIS) P19.11(CHASSIS) P19.12(CHASSIS) P23.6(VSS) P23.10(M1) P23.11(M2) P23.12(M3) P23.13(M4) Q2.3(D) Q5.2(S) Q6.1(S1) Q6.4(S2) Q7.3(D) R85.2 R86.2 R87.2 R98.2 R99.2 R100.1 R101.2 R102.2 R103.2 R104.2 R105.2 R106.2 R108.2 R110.2 R111.2 R115.1 R123.2 R125.2 R127.2 R132.1 R136.2 R149.1 R169.2 R209.1 RN5.8(RA2) RN7.1(RA1) RN7.2(RB1) RN7.3(RC1) RN7.4(RD1) RN8.3(RC1) S2.2 SP1.1 SP2.1 SP3.1 U17.9(GNDXD) U17.16(GNDODA) U18.4(GND) U18.9(PAD) U19.9(GND) U19.10(GND) U19.11(GND) U19.12(GND) U20.4(GND) U20.9(PAD) U21.5(GND) U21.9(EPAD) U22.5(GND) U22.9(EPAD) U23.5(GND) U23.9(EPAD) U24.2(GND) U25.2(GND) U26.2(GND) U27.2(GND) U28.2(GND) U29.4(R4IN) U29.5(R5IN) U29.24(GND) U29.33(EPAD) U30.2(GND) U31.4(GND) X3.2 X3.4 ; also on sheet 2 3 4 5 6 7 8
V3P3_Q7_PCIECLK_A: C105.2 FB2.2 U17.15(VDDODA)
VCC_RTC: C198.1 E6.2 ; also on sheet 2
100MHz_CLK_S0: RN5.3(RC1) U17.2(S0)
100MHz_CLK_S1: RN5.2(RB1) U17.3(S1)
100MHz_CLK_SS2: RN5.1(RA1) U17.4(SS2)
100MHz_IREF: R100.2 U17.10(IREF)
CARRIER_EEPROM_WP: E11.2 R149.2 U31.7(WP)
CLK_OE: R95.1 U17.8(OE)
CLK_PD#: R97.1 U17.7(PD#)
DBG_UART_RXD: U25.5(A1) U30.4(A2) ; also on sheet 2
DBG_UART_TXD: U25.4(A2) U30.5(A1) ; also on sheet 2
DEBUGSEL: E4.1 Q6.2(G1) R222.2 RN8.6(RC2) ; also on sheet 7
EPR_A0: R226.1 RN7.8(RA2) U31.1(A0)
EPR_A1: R227.1 RN7.7(RB2) U31.2(A1)
EPR_A2: R225.1 RN7.6(RC2) U31.3(A2)
FB_LDO_1V5: R135.1 R136.1 U23.6(ADJ)
FB_LDO_1V8: R126.1 R127.1 U21.6(ADJ)
FB_LDO_2V8: R131.1 R132.2 U22.6(ADJ)
G_REVR_PR: Q7.1(G) R79.1 R80.2 R206.2
I2C1_SCL: U31.6(SCL) ; also on sheet 2 7
I2C1_SDA: U31.5(SDA) ; also on sheet 2 7
I2C4_SCL: P11.30(SMB_CLK) ; also on sheet 6 7 8
I2C4_SDA: P11.32(SMB_DATA) ; also on sheet 6 7 8
IDT_CLK0_N: R89.1 U17.19(CLK0_N)
IDT_CLK0_P: R88.1 U17.20(CLK0_P)
IDT_CLK1_N: R91.1 U17.17(CLK1_N)
IDT_CLK1_P: R90.1 U17.18(CLK1_P)
IDT_CLK2_N: R93.1 U17.13(CLK2_N)
IDT_CLK2_P: R92.1 U17.14(CLK2_P)
IDT_CLK3_N: R96.1 U17.11(CLK3_N)
IDT_CLK3_P: R94.1 U17.12(CLK3_P)
IDT_CLK_X1: C106.1 U17.5(X1/ICLK) X3.1
IDT_CLK_X2: C107.1 U17.6(X2) X3.3
IDT_T_CLK1_N: R91.2 R103.1 R232.2
IDT_T_CLK1_P: R90.2 R102.1 R231.2
IDT_T_CLK2_N: R93.2 R105.1 ; also on sheet 7
IDT_T_CLK2_P: R92.2 R106.1 ; also on sheet 7
IDT_T_CLK3_N: R96.2 R99.1
IDT_T_CLK3_P: R94.2 R104.1
LED_PR_ENN: DS4.CATHODE R77.1 R78.1
LED_USBSERIALEN: R150.2 U11.13(I)
mPCIe_PERST: P11.22(PERST#) R87.1 R192.2 ; also on sheet 7
mPCIE_USB_DN: L3.4 P11.36(USB_D-)
mPCIE_USB_DP: L3.3 P11.38(USB_D+)
MUX_PCI_USB_DN: L3.1 ; also on sheet 4
MUX_PCI_USB_DP: L3.2 ; also on sheet 4
nUSBSERIALEN: Q6.5(G2) Q6.6(D1) RN8.8(RA2) U30.6(OE)
P_AGND: C124.2 C125.2 R117.2 S2.1 U19.1(AGND)
PCI_1V5: C97.1 C98.1 C99.1 C103.1 P11.6(+1.5V_1) P11.28(+1.5V_2) P11.48(+1.5V_3) R228.2
PCIE1_REF_CLKN: P11.11(REFCLK-) R85.1 R232.1 R233.1
PCIE1_REF_CLKP: P11.13(REFCLK+) R86.1 R230.1 R231.1
PCIE1_RXN_N: P11.23(PER_N0) ; also on sheet 2
PCIE1_RXN_P: P11.25(PER_P0) ; also on sheet 2
PCIE1_TXN_N: P11.31(PET_N0) ; also on sheet 2
PCIE1_TXN_P: P11.33(PET_P0) ; also on sheet 2
PCIE_EXT_REF_CLKN: R89.2 R98.1 ; also on sheet 2
PCIE_EXT_REF_CLKP: R88.2 R101.1 ; also on sheet 2
PCIE_INT_REF_CLKN: R233.2 ; also on sheet 2
PCIE_INT_REF_CLKP: R230.2 ; also on sheet 2
PHY_2V5: R73.1 ; also on sheet 2
PLED_A: DS4.ANODE R74.2
PMIC_ON_REQ: R109.1 R144.2 R170.2 ; also on sheet 2 7 8
POR_B: R192.1 ; also on sheet 2 5 7 8
REVR_PR: D9.CATHODE R72.2 R79.2 R81.2 R84.2 ; also on sheet 2
RS232_RXD_UART1: P16.3 U29.2(R2IN)
RS232_RXD_UART4: P19.3 U29.3(R3IN)
RS232_TXD_UART1: P16.1 U29.7(T2OUT)
RS232_TXD_UART4: P19.1 U29.8(T3OUT)
RS232DB_LED: DS2.ANODE R148.2
RS232DB_LEDCAT: DS2.CATHODE U11.12
RS232DB_RXD_DBG: P15.3 U29.1(R1IN)
RS232DB_TXD_DBG: P15.1 U29.6(T1OUT)
S_REVR_PR: Q7.2(S) R73.2 R77.2 R78.2 R80.1
SD2_CLK: R143.2 ; also on sheet 2
SD2_CMD: R145.2 ; also on sheet 2
SD2_DATA0: R140.2 ; also on sheet 2
SD2_DATA1: R137.2 ; also on sheet 2
SD2_DATA2: R141.2 ; also on sheet 2
SD2_DATA3: R142.2 ; also on sheet 2
SD2_nCD: P23.9(CD#) R9.2 ; also on sheet 2
SDCARD_CLK: P23.5(CLK) R143.1 RN6.7(R6) U27.3(IO2)
SDCARD_CMD: P23.3(CMD) R145.1 RN6.8(R7) U28.6(IO4)
SDCARD_DAT0: P23.7(DAT0) R140.1 RN6.1(R1) U27.1(IO1)
SDCARD_DAT1: P23.8(DAT1) R137.1 RN6.2(R2) U27.6(IO4)
SDCARD_DAT2: P23.1(DAT2) R141.1 RN6.3(R3) U28.1(IO1)
SDCARD_DAT3: P23.2(DAT3) R142.1 RN6.4(R4) U28.4(IO3)
SERIAL_VBUS: C142.1 P13.1(VBUS) R222.1 U24.7(REGIN) U24.8(VBUS) U26.4(IO3)
SIM1_CLK: P11.12(UIM_CLK) P12.3(CLK)
SIM1_IO: P11.10(UIM_DATA) P12.7(IO)
SIM1_RST: P11.14(UIM_RESET) P12.2(RST)
SIM1_VCC: C196.2 P11.8(UIM_PWR) P12.1(VCC)
SIM1_VPP: P11.16(UIM_VPP) P12.6(VPP)
SP_PMP_C1N: C156.2 U29.23(C1-)
SP_PMP_C1P: C156.1 U29.28(C1+)
SP_PMP_C2N: C151.2 U29.30(C2-)
SP_PMP_C2P: C151.1 U29.29(C2+)
SP_PMP_VN: C154.1 U29.31(V-)
SP_PMP_VP: C157.1 U29.27(V+)
UART1_R2OUT: R247.2 U29.17(R2OUT)
UART1_RXD/ECSPI3_SCLK: R247.1 ; also on sheet 2 7
UART1_T2IN: R245.2 U29.11(T2IN)
UART1_TXD/ECSPI3_MOSI: R245.1 ; also on sheet 2 7
UART4_R3OUT: R248.2 U29.15(R3OUT)
UART4_RXD: R248.1 ; also on sheet 2 7
UART4_T3IN: R246.2 U29.10(T3IN)
UART4_TXD: R246.1 ; also on sheet 2 7
USBSERIAL_3V45: C140.1 C141.1 C144.1 RN8.4(RD1) U24.5(VIO) U24.6(VDD) U25.7(VCCB)
USBSERIAL_DN: P13.2(D-) U24.4(DN) U26.6(IO4)
USBSERIAL_DP: P13.3(D+) U24.3(DP) U26.1(IO1)
USBSERIAL_nRST: RN8.5(RD2) U24.9(RST#)
USBSERIALEN: Q6.3(D2) R150.1 RN8.7(RB2) U25.6(OE)
V_RTC: D4.CATHODE D8.CATHODE E6.1
V_SOM: C14.1 C15.1 C16.1 C17.1 C18.1 C19.1 C121.2 C122.2 C134.1 C136.1 C138.1 C208.1 C209.1 C218.1 C219.1 C223.1 E7.1 E8.1 Q3.5(D) Q3.6(D) Q3.7(D) Q3.8(D) Q3.9(D-pad) R112.1 R118.1 R129.2 R134.2 R223.1 U21.1(Vin1) U21.2(Vin2) U22.1(Vin1) U22.2(Vin2) U23.1(Vin1) U23.2(Vin2) ; also on sheet 2 8
V_SOM_BOOT: C120.1 U19.5(BOOT)
V_SOM_DSCHG: Q2.2(S) R118.2
V_SOM_EN: R81.1 R113.2 R115.2 U19.13(EN) ; also on sheet 7
V_SOM_FB: C123.2 R116.1 R117.1 U19.2(FB)
V_SOM_L: C123.1 C172.2 C197.2 E7.2 E8.2 L5.2 Q3.1(S) Q3.2(S) Q3.3(S) R116.2 R119.1
V_SOM_LX: C120.2 L5.1 U19.6(SW)
V_SOM_PG: Q2.1(G) R114.2 U19.4(PGOOD)
V_SOM_PVCC: C125.1 U19.3(PVCC)
V_SOM_SS: C124.1 U19.14(SS)
VCOIN: BH1.2(PLUS) D4.ANODE
VDC_IN: C108.1 C109.1 C113.1 C114.1 C117.1 C118.1 C119.1 C130.1 C131.1 D5.CATHODE J2.1(CENTRAL) R74.1 R108.1 R114.1 R121.1 R161.1 R206.1 U18.2(Vin) U19.7(VIN) U19.8(VIN) U20.2(Vin)
VSB_1V5: C139.1 R135.2 R228.1 U23.7(Vout1) U23.8(Vout2) ; also on sheet 7
VSB_1V5_EN: R133.2 R134.1 U23.4(EN)
VSB_1V8: C135.1 R124.1 R126.2 U21.7(Vout1) U21.8(Vout2) ; also on sheet 7
VSB_1V8_EN: R144.1 R223.2 U21.4(EN)
VSB_1V8_PGOOD: R124.2 R128.2 U21.3(PGOOD)
VSB_2V8: C137.1 R130.1 R131.2 U22.7(Vout1) U22.8(Vout2) ; also on sheet 7
VSB_2V8_EN: R128.1 R129.1 U22.4(EN)
VSB_2V8_PGOOD: R130.2 R133.1 U22.3(PGOOD)
VSOM_BP_EN#: E9.2 Q3.4(G) R119.2
VSOM_LED: DS1.ANODE R112.2

Not connected (* = marked no-connect by the designer): P11 1(WAKE#)* 3(RSVD1)* 5(RSVD2)* 7(CLKREQ#)* 17(RSVD3)* 19(RSVD4)* 20(RSVD18)* 42(LED_WWAN#)* 43(RSVD8)* 44(LED_WLAN#)* 45(RSVD9)* 46(LED_WPAN#)* 47(RSVD10)* 49(RSVD11)* 51(RSVD12)*; P12 4(RSVD4)* 8(RSVD8)*; P13 4(ID)*; P15 2* 4* 5* 6* 7*; P16 2* 4* 5* 6* 7*; P19 2* 4* 5* 6* 7*; RN5 4(RD1)* 5(RD2)*; RN6 6(R5)* 9(R8)*; RN7 5(RD2)*; U23 3(PGOOD)*; U24 1(RI)* 10(NC)* 11(GPIO3)* 12(GPIO2)* 13(GPIO1)* 14(GPIO0)* 15(SUSPEND#)* 16(VPP)* 17(SUSPEND)* 18(CTS)* 19(RTS)* 22(DSR)* 23(DTR)* 24(DCD)*; U26 3(IO2)* 5(VBUS)*; U27 4(IO3)*; U28 3(IO2)*; U29 9(NC)* 13(R5OUT)* 14(R4OUT)* 16(NC)* 19(R2OUTB)* 20(INVALID)* 25(NC)* 32(NC)*

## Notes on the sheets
sheet 9
- mini PCIe socket & SIM socket
- DNP
- DNP
- DNP
- DNP
- Validate if those resistors
  required after bring up
- DNP
- PCIe clock generator
- Make trace to VDD AsShortAsPossible,
  decoupling caps and FB can be placed on back
  and placed ACAP to VDD
- 100 MHzCLK diff pairs
  100 ohm impedance
  28 mil intralane missmatch
sheet 10
- DC input
- 5V0_PER
- MAX 16V
- RTC battery
- min 6.8uH
- 12V domain
- DNP
- H=4.2mm
- Vout=Vfb*(1+Rt/Rb)=
  0.92*(1+32.4/12.4)=3.32V@3A
- 12V domain
- up to 24V
- Install by default
- DNP
- V_SOM
- V_SOM discharge
- Vout = 0.7x(1+Rup/Rdn)=0.7*(1+215/49.9)=3.72@9A
- to 100 mill header
- 12V domain
- DNP
- >1.6V
- 3V3_PER
- Vin 4.5-18V
- 10mA OD
- Current measure
- DNP
- 12V domain
- Vgs up to 12V
- DNP
- DNP
- DNP
- DNP
- DNP
- DNP
- 3V3_AW
- VSB_1V5, VSB_1V8 & VCC_2V8 CSI sources
- DNP
- 1206
- H=4.2mm
- DNP
- Vout=Vfb*(1+Rt/Rb)=
  0.92*(1+32.4/12.4)=3.32V@3A
- Vout=Vfb*(1+Rt/Rb)=0.8*(1+13.3/10)=1.86V
- EN=2.8V
- DNP
- 12V domain
- DNP
- DNP
- Vout=Vfb*(1+Rt/Rb)=0.8*(1+16.5/6.49)=2.8V
- LED-Reverse Position
- DNP
- Vout=Vfb*(1+Rt/Rb)=0.8*(1+9.1/10)=1.528V
- DNP
- DNP
- DNP
- DNP
sheet 11
- Serial debug console
- Micro-SD socket (bootable)
- DNP
- DEBUG PORT
  (microUSB2.0 Type B)
  UART over USB
- In
- Out
- O
- O
- DNP
- USB console connection indicator
- Jumper removed: Automatic Mode
      Debug over USB when USB host
  provides VBUS
      Debug over RS-232 when USB VBUS not
  available
  Jumper assembled: Force RS232
- TX-Out
- RX-In
- Carrier-board EEPROM
- RS232
- DEBUG PORT
  (Compulab Proprietry)
  UART over RS-232
- 3.3V x 2mA = 6.6mW
- I2C slave address: 0x54..0x57
- RS-232
- RS-232
sheet 12
- For PCIe module
- Stitching capacitors
- For carrier-board stand-offs
- UCM-iMX8M-Mini spacers
- 2XSPASER: 383B52520S
- Heatsink provision
- 4mm
